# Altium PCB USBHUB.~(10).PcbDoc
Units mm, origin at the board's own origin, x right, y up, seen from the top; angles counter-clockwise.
Board outline 152.4 x 101.6 mm, 2 copper layers (Top Layer, Bottom Layer); 37 components, 26 nets, 161 pads, 0 vias.
Unrouted connection lines stored in the file: 30.
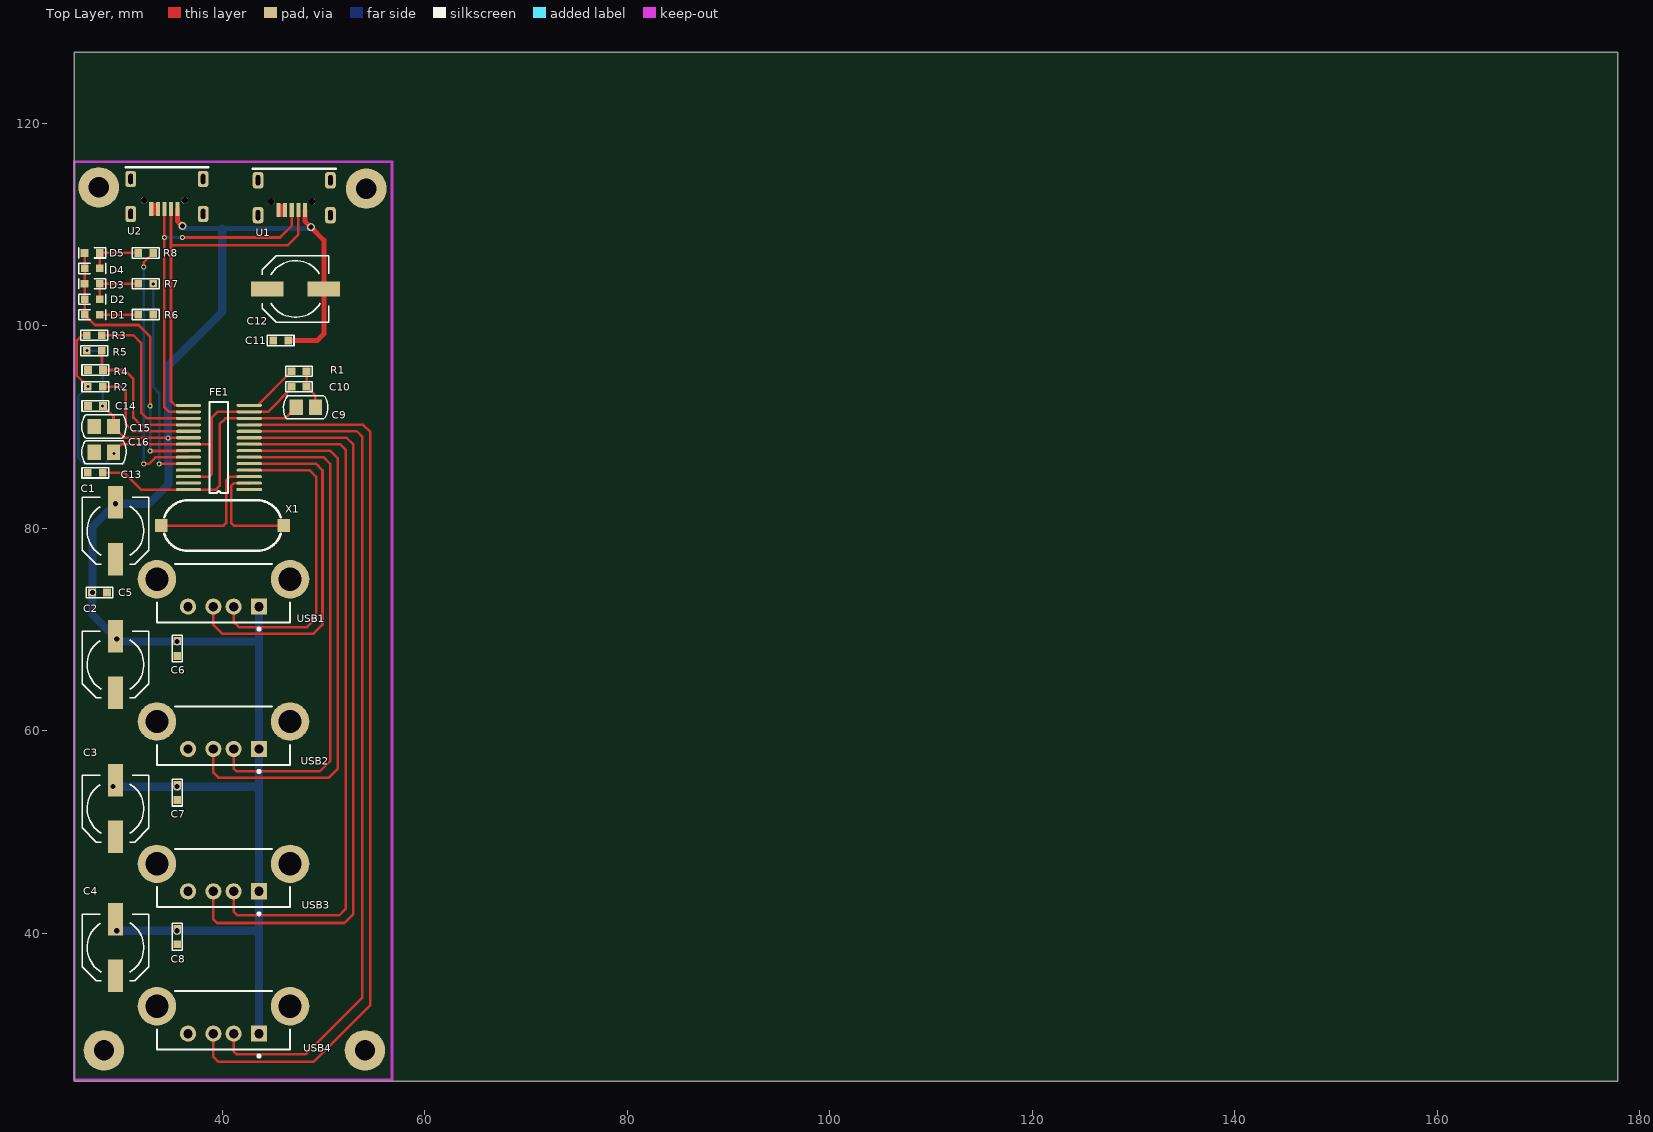
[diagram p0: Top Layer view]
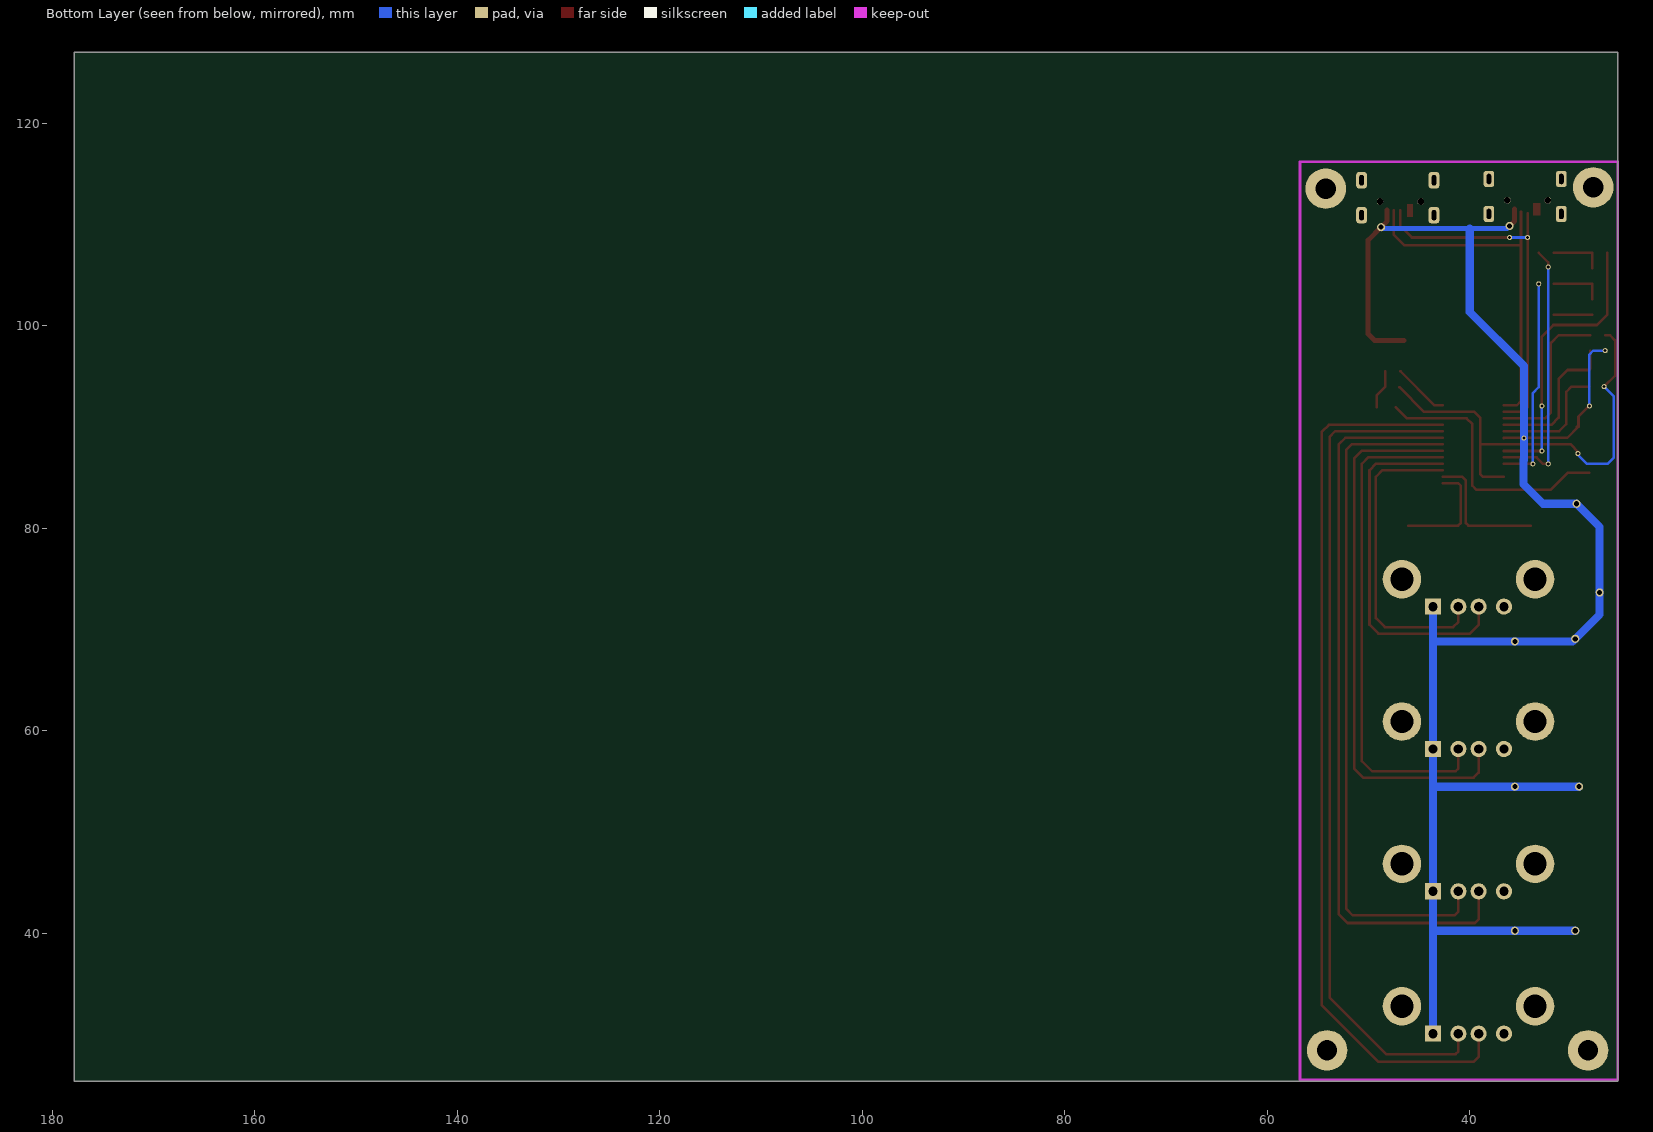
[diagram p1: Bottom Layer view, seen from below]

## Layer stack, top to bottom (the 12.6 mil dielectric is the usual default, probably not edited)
Top Layer: signal copper 0.0356
Dielectric: dielectric 0.32, FR-4, Dk 4.8
Bottom Layer: signal copper 0.0356

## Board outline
25.4,25.4 177.8,25.4 177.8,127 25.4,127

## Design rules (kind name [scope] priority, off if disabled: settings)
Clearance [All] p1: gap=0.254
PolygonConnect [All] p1: connectstyle=Relief reliefconductorwidth=0.254 reliefentries=4 polygonreliefangle="90 Angle"
RoutingVias [All] p1: holewidth=0.711 width=1.27 viastyle="Through Hole" minholewidth=0.711 minwidth=1.27 maxholewidth=0.711 maxwidth=1.27
SilkscreenOverComponentPads [All] p1: minsilkscreentomaskgap=0.254
SolderMaskExpansion [All] p1: expansion=0.102
TestPointUsage [All] p1: valid=0 allowmultiple=FALSE
Testpoint [All] p1: side=15 testpointundercomponent=TRUE minsize=1.016 maxsize=2.54 preferedsize=1.524 minholesize=0 maxholesize=1.016 preferedholesize=0.813 testpointgrid=0.025 style=1023 order=0123456789
Width [All] p1: maxlimit=2 minlimit=0.254 preferedwidth=0.254
23 further rules are at their usual default settings.

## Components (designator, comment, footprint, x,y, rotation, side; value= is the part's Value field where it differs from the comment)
C1 "Cap_Pol" cap_220uF/16V 29.464,79.756 r90 top
C2 "Cap_Pol" cap_220uF/16V 29.464,66.548 r90 top
C3 "Cap_Pol" cap_220uF/16V 29.464,52.324 r90 top
C4 "Cap_Pol" cap_220uF/16V 29.464,38.608 r90 top
C5 "Cap1" 0603 27.94,73.66 r180 top
C6 "Cap1" 0603 35.56,68.072 r90 top
C7 "Cap1" 0603 35.56,53.848 r90 top
C8 "Cap1" 0603 35.56,39.624 r90 top
C9 "Cap1" 2012[0805]-C 48.26,91.948 r180 top
C10 "Cap1" 0603 47.647,93.98 r180 top
C11 "Cap1" 0603 45.72,98.552 r0 top
C12 "Cap_Pol" cap_220uF/16V 47.244,103.632 r0 top
C13 "Cap1" 0603 27.534,85.471 r180 top
C14 "Cap1" 0603 27.429,92.075 r0 top
C15 "Cap1" 2012[0805]-C 28.321,90.043 r0 top
C16 "Cap1" 2012[0805]-C 28.321,87.503 r0 top
D1 "LED" 0603-Polar 27.111,101.092 r0 top
D2 "LED" 0603-Polar 27.111,102.616 r0 top
D3 "LED" 0603-Polar 27.216,104.14 r180 top
D4 "LED" 0603-Polar 27.111,105.664 r0 top
D5 "LED" 0603-Polar 27.216,107.188 r180 top
FE1 "FE1.1s" SSOP-28 42.672,83.82 r180 top
R1 "Res1" 0603 47.647,95.504 r180 top
R2 "Res1" 0603 27.534,93.98 r180 top
R3 "Res1" 0603 27.432,99.06 r180 top
R4 "Res1" 0603 27.429,95.631 r0 top
R5 "Res1" 0603 27.432,97.536 r180 top
R6 "Res1" 0603 32.512,101.092 r180 top
R7 "Res1" 0603 32.512,104.14 r180 top
R8 "Res1" 0603 32.512,107.188 r180 top
U1 "Micro-USB" MICRO-USB-F 47.117,113.665 r180 top
U2 "Micro-USB" MICRO-USB-F 34.544,113.792 r180 top
USB1 "USB" USB2.5-2V4A 40.132,76.454 r90 top
USB2 "USB" USB2.5-2V4A 40.132,62.399 r90 top
USB3 "USB" USB2.5-2V4A 40.132,48.345 r90 top
USB4 "USB" USB2.5-2V4A 40.132,34.29 r90 top
X1 "12M" XTAL_SMD 37.592,80.264 r0 top

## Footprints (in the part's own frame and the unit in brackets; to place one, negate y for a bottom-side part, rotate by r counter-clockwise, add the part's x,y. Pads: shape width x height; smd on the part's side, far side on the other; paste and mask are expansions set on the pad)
0603 [mil]
  rect 30x30 smd: 1(-27,0) 2(31.5,0)
  silkscreen extent -50,-20 54,20
0603-Polar [mil]
  rect 30x30 smd: 1(-27,0) 2(31.5,0)
  silkscreen extent -50,-20 54,20
2012[0805]-C [mm] "Chip Resistor; Body 2.0 x 1.3 mm (LxW typ)"
  rect 1.3x1.5 smd: 1(-0.95,0) 2(0.95,0)
  silkscreen extent -2.17,-1.16 2.21,1.14
cap_220uF/16V [mm]
  rect 3.2x1.5 smd: 1(-2.794,0) 2(2.8,0)
  silkscreen extent -3.3,-3.3 3.3,3.3
MICRO-USB-F [mm]
  rrect50% 1.05x1.6 hole 0.45 slot 1 at 90 deg: 0(-3.575,-0.7) 0(-3.575,2.75) 0(3.575,-0.7) 0(3.575,2.75)
  round 0.65 hole 0.65: 0(-1.75,1.4) 0(2.25,1.4)
  rect 0.4x1.4 smd: 1(-1.05,2.25) 2(-0.403,2.25) 3(0.246,2.25) 4(0.897,2.25) 5(1.546,2.25)
  silkscreen extent -4.08,-1.85 4.08,-1.85
SSOP-28 [mm]
  rect 2.5x0.3 smd: 1(0,0)
  oval 2.5x0.3 smd: 2(0,-0.64) 3(0,-1.28) 4(0,-1.92) 5(0,-2.56) 6(0,-3.2) 7(0,-3.84) 8(0,-4.48) 9(0,-5.12) 10(0,-5.76) 11(0,-6.4) 12(0,-7.04) 13(0,-7.68) 14(0,-8.32) 15(6,-8.32) 16(6,-7.68) 17(6,-7.04) 18(6,-6.4) 19(6,-5.76) 20(6,-5.12) 21(6,-4.48) 22(6,-3.84) 23(6,-3.2) 24(6,-2.56) 25(6,-1.92) 26(6,-1.28) 27(6,-0.64) 28(6,0)
  silkscreen extent 2.08,-8.64 3.92,0.32
USB2.5-2V4A [mm] "Connector; USB1.1, Type A, Thru-Hole; 4 Position; Vertical"
  rect 1.6x1.6 hole 0.92: 1(-4.19,-3.5)
  round 1.6 hole 0.92: 2(-4.19,-1) 3(-4.19,1) 4(-4.19,3.5)
  round 3.8 hole 2.3: 5(-1.48,6.57) 6(-1.48,-6.57)
  silkscreen extent -6.53,-6.57 0,6.57, body extent -5.76,-6.57 0,6.57, height 15
XTAL_SMD [mm]
  rect 1.27x1.27 smd: 1(-3.61,0) 2(8.49,0)
  silkscreen extent -3.33,-2.5 8.21,2.5

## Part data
C1 C2 C3 C4 C5 C6 C7 C8 C9 C10 C11 C12 C13 C14 C15 C16: "Capacitor"
D1 D2 D3 D4 D5: library part LED1, "Typical INFRARED GaAs LED"
R1 R2 R3 R4 R5 R6 R7 R8: "Resistor"
X1: library part XTAL_1, "Crystal Oscillator"

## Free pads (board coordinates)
  round 0.5 hole 0.3: 4(32.893,92.075) 7(32.258,105.791) 9(32.258,86.36) 10(32.893,87.63) 11(33.198,104.14) 12(33.782,86.36) 14(26.734,93.98) 15(29.337,87.376) 16(28.194,92.075) 17(26.632,97.536) 23(36.068,108.712) 24(34.298,108.712) 33(34.671,88.9)
  round 0.8 hole 0.5: 21(36.068,109.855) 22(48.768,109.728) 25(29.464,82.423) 26(29.591,69.088) 27(29.21,54.483) 28(29.591,40.259) 29(27.178,73.66) 30(35.56,68.834) 31(35.56,54.483) 32(35.56,40.259)
  round 4 hole 2: 34(27.813,113.665) 35(54.229,113.538) 36(54.102,28.448) 37(28.321,28.448)

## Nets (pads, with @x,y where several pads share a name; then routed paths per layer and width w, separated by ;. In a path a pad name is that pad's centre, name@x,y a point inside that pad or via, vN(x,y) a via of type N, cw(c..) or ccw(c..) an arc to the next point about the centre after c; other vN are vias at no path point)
GND: C1.1 C2.1 C3.1 C4.1 C5.1 C6.1 C7.1 C8.1 C9.1 C10.1 C11.1 C12.1 C13.2 C14.1 C15.1 C16.1 R1.1 R4.1 R6.1 U1.4 U1.5 U2.4 U2.5 USB1.4 USB1.5 USB1.6 USB2.4 USB2.5 USB2.6 USB3.4 USB3.5 USB3.6 USB4.4 USB4.5 USB4.6 | length 3.9
  Top Layer w0.254: R1.1 C10.1 49.21,93.103 C9.1
NetD1_1: D1.1 D2.1 D3.2 D4.1 D5.2 FE1.22 pad.4 pad.10 | length 28.5
  Top Layer w0.254: D5.2 D3.2 26.416,101.101 D1.1 27.441,100.076 31.75,100.076 32.893,98.933 pad.4 ; pad.10 FE1.22@36.642,87.63
  Bottom Layer w0.254: pad.10 pad.4
NetD1_2: D1.2 R6.2 | length 3.8
  Top Layer w0.254: D1.2 R6.2
NetD2_2: D2.2 D3.1 R7.2 | length 5.3
  Top Layer w0.254: D2.2@27.902,102.625 D3.1 R7.2
NetD4_2: D4.2 D5.1 R8.2 | length 5.3
  Top Layer w0.254: D4.2@27.902,105.673 D5.1 R8.2
NetFE1_2: FE1.2 X1.2 | length 10.9
  Top Layer w0.254: FE1.2 41.153,84.46 40.894,84.201 40.894,80.518 41.148,80.264 X1.2
NetFE1_3: FE1.3 X1.1 | length 13.1
  Top Layer w0.254: X1.1 40.132,80.264 40.386,80.518 40.386,84.709 40.777,85.1 FE1.3
NetFE1_4: FE1.4 USB1.2 | length 31.1
  Top Layer w0.254: USB1.2 41.132,70.755 41.656,70.231 48.387,70.231 49.276,71.12 49.276,85.09 48.626,85.74 FE1.4
NetFE1_5: FE1.5 USB1.3 | length 36.1
  Top Layer w0.254: USB1.3 39.132,70.469 40.005,69.596 49.022,69.596 49.911,70.485 49.911,85.725 49.256,86.38 FE1.5
NetFE1_6: FE1.6 USB2.2 | length 49.6
  Top Layer w0.254: USB2.2 41.132,56.277 41.402,56.007 49.657,56.007 50.673,57.023 50.673,86.36 50.013,87.02 FE1.6
NetFE1_7: FE1.7 USB2.3 | length 54.9
  Top Layer w0.254: USB2.3 39.132,55.864 39.624,55.372 50.546,55.372 51.435,56.261 51.435,86.868 50.643,87.66 FE1.7
NetFE1_8: FE1.8 USB3.2 | length 68.6
  Top Layer w0.254: USB3.2 41.132,42.18 41.529,41.783 51.562,41.783 52.197,42.418 52.197,87.757 51.654,88.3 FE1.8
NetFE1_9: FE1.9 USB3.3 | length 74
  Top Layer w0.254: USB3.3 39.132,41.386 39.497,41.021 52.07,41.021 52.959,41.91 52.959,88.265 52.284,88.94 FE1.9
NetFE1_10: FE1.10 USB4.2 | length 83.7
  Top Layer w0.254: USB4.2 41.132,28.337 41.402,28.067 48.26,28.067 53.848,33.655 53.848,89.027 53.295,89.58 FE1.10
NetFE1_11: FE1.11 USB4.3 | length 89.2
  Top Layer w0.254: USB4.3 39.132,27.797 39.624,27.305 49.022,27.305 54.61,32.893 54.61,89.535 53.925,90.22 FE1.11
NetFE1_14: FE1.14 R1.2 | length 5.6
  Top Layer w0.254: FE1.14 43.483,92.14 R1.2
NetFE1_15: FE1.15 U1.2 U2.2 | length 36
  Top Layer w0.254: U2.2@34.947,111.252 34.947,107.95 ; FE1.15 35.368,92.14 34.947,92.561 34.947,107.95 ; U1.2 47.52,108.988 46.482,107.95 34.947,107.95
NetFE1_16: FE1.16 pad.23 pad.24 U1.3 U2.3 | length 36.3
  Top Layer w0.254: U2.3@34.298,111.125 34.298,91.94 34.738,91.5 FE1.16 ; pad.23 45.72,108.712 46.871,109.863 U1.3
  Bottom Layer w0.254: pad.24 pad.23
NetFE1_17: FE1.17 R3.1 | length 16
  Top Layer w0.254: R3.1 31.242,99.06 32.004,98.298 32.004,91.44 32.584,90.86 FE1.17
NetFE1_18: FE1.18 R4.2 R5.1 | length 14.9
  Top Layer w0.254: R5.1 28.118,96.266 28.118,95.742 R4.2 30.353,95.631 31.242,94.742 31.242,90.932 31.954,90.22 FE1.18
NetFE1_19: FE1.19 R2.1 | length 12.1
  Top Layer w0.254: R2.1 29.972,93.98 30.48,93.472 30.48,90.297 31.197,89.58 FE1.19
NetFE1_23: FE1.23 pad.7 pad.9 R8.1 | length 25.9
  Top Layer w0.254: pad.9 32.766,86.36 33.401,86.995 36.647,86.995 FE1.23 ; pad.7 32.258,106.248 R8.1
  Bottom Layer w0.254: pad.9 pad.7
NetFE1_24: FE1.24 pad.11 pad.12 R7.1 | length 20.9
  Top Layer w0.254: pad.12 36.652,86.36 FE1.24
  Bottom Layer w0.254: pad.11 33.198,93.929 33.782,93.345 pad.12
VCC1_8: C9.2 C13.1 FE1.12 FE1.28 | length 26.7
  Top Layer w0.254: C13.1 30.353,85.471 32.004,83.82 FE1.28 39.37,83.82 39.751,84.201 39.751,90.297 40.314,90.86 FE1.12 46.222,90.86 C9.2
VCC3_3: C10.2 C16.2 FE1.13 FE1.21 FE1.26 pad.14 pad.15 R2.2 R3.2 | length 45.1
  Top Layer w0.254: R3.2 26.162,99.06 25.654,98.552 25.654,95.06 R2.2 ; C16.2 30.068,88.3 FE1.21 38.954,88.3 ; FE1.26 38.745,85.1 38.989,85.344 38.989,90.932 39.557,91.5 FE1.13 44.51,91.5 C10.2@46.952,93.942
  Bottom Layer w0.254: pad.14 25.781,93.027 25.781,86.995 26.416,86.36 28.448,86.36 29.337,87.249 pad.15
VCC5: C1.2 C2.2 C3.2 C4.2 C5.2 C6.2 C7.2 C8.2 C11.2 C12.2 C14.2 C15.2 FE1.20 pad.16 pad.17 pad.21 pad.22 pad.25 pad.26 pad.27 pad.28 pad.29 pad.30 pad.31 pad.32 pad.33 R5.2 U1.1 U2.1 USB1.1 USB2.1 USB3.1 USB4.1 | length 182.3
  Top Layer w0.254: C14.2 29.271,91.033 C15.2 ; C15.2@29.464,90.043 C15.2 ; FE1.20@36.632,88.9 FE1.20 30.374,88.94 C15.2
  Top Layer w0.5: U2.1 35.594,110.329 pad.21 ; C11.2 49.403,98.552 50.044,99.193 C12.2 50.044,108.452 pad.22 48.167,110.329 U1.1
  Bottom Layer w0.254: pad.17 27.813,97.536 28.194,97.155 pad.16
  Bottom Layer w0.5: pad.21 36.312,109.611 40.005,109.611 48.651,109.611 pad.22
  Bottom Layer w0.8: pad.27 43.632,54.483 ; pad.28 43.632,40.259 ; 40.005,109.611 40.005,101.346 34.671,96.012 34.671,86.749 34.686,86.734 34.686,84.343 32.766,82.423 pad.25 27.178,80.137 27.178,71.501 29.845,68.834 43.505,68.834 ; USB4.1 USB3.1 43.632,54.483 ; USB1.1 USB2.1 43.632,54.483
pads on no net: FE1.1 FE1.25 FE1.27 U1.0 U2.0

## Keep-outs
Keep-Out Layer:
  lines w0.254: 25.4,25.527 56.769,25.527 56.769,116.205 25.4,116.205 25.4,25.527

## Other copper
Top Layer:
  rectangle net GND: 45.593,110.744 46.228,112.014
  rectangle net GND: 33.02,110.871 33.782,112.141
